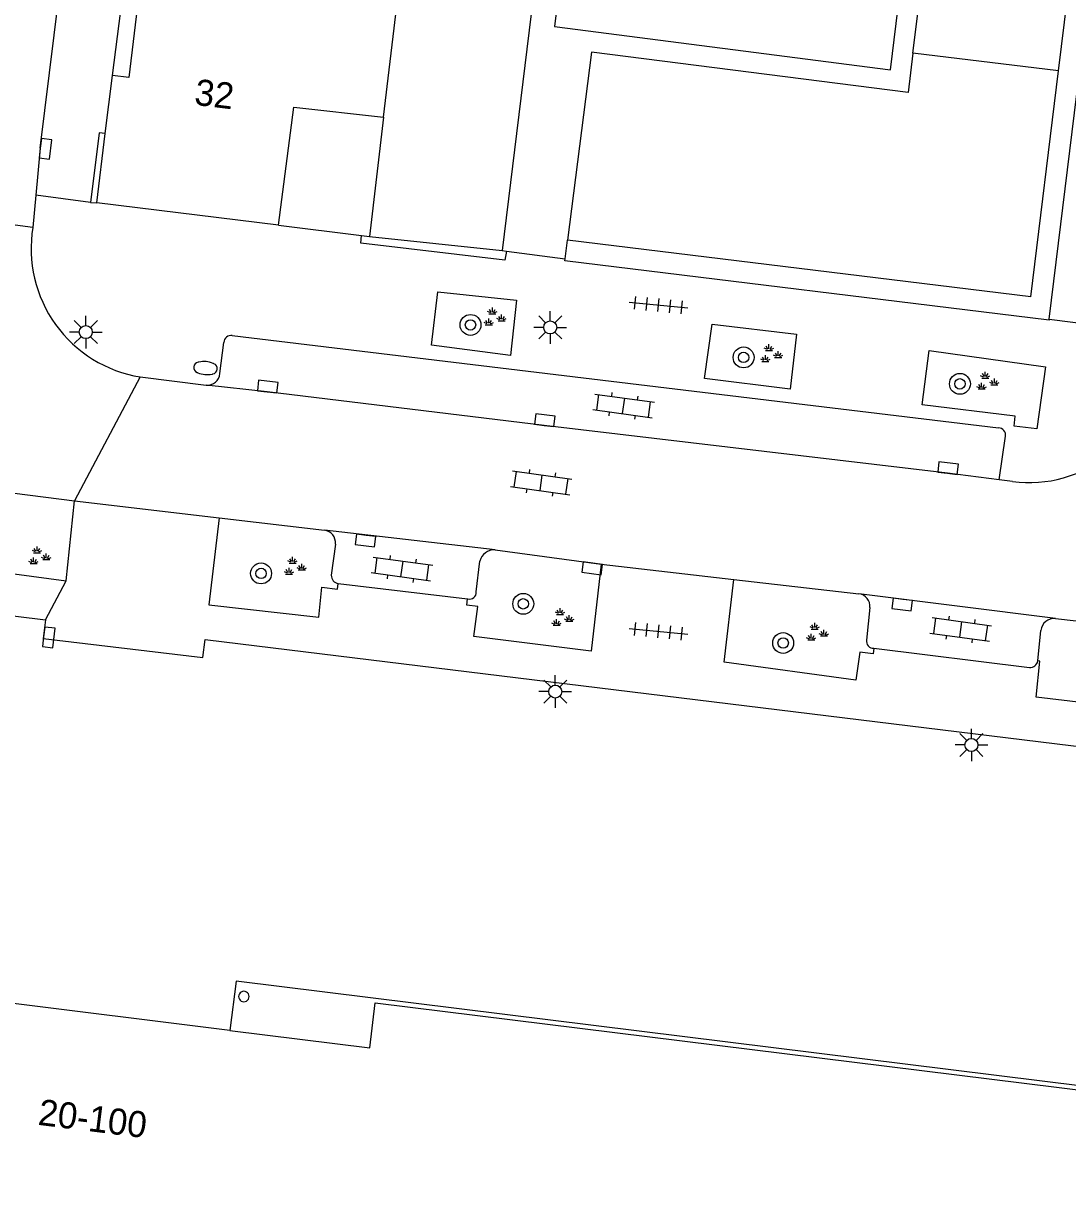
# Model space of a CAD drawing. Extents: x 131000 to 133014, y 396499 to 399001.
# Drawn here: x 132127.74 to 132167.75, y 396701.57 to 396746.51 of the extents above; entities that cross this region are included whole.
import ezdxf

# ---------------------------------------------------------------- set-up
doc = ezdxf.new("R2010")
doc.units = 0
for name, color, linetype in [('gg-afsc-erfafscheiding', 7, 'Continuous'), ('gg-anno-huisnummerreeks BGT', 7, 'Continuous'), ('gg-bbg-hoofdgebouw', 7, 'Continuous'), ('gg-bbg-luifel en loopbrug', 7, 'Continuous'), ('gg-bbg-onder overbouw', 7, 'Continuous'), ('gg-bbg-pand overbouw', 7, 'Continuous'), ('gg-bbg-pilaar onder overbouw', 7, 'Continuous'), ('gg-knt-verharding', 7, 'Continuous'), ('gg-knt-verharding nz', 7, 'Continuous'), ('gt-grn-groengrens', 7, 'Continuous'), ('gt-grn-weggrens', 7, 'Continuous'), ('gt-symb-boom', 7, 'Continuous'), ('gt-symb-brandkraan', 7, 'Continuous'), ('gt-symb-groenvak', 7, 'Continuous'), ('gt-symb-klinker verharding', 7, 'Continuous'), ('gt-symb-kolk', 7, 'Continuous'), ('gt-symb-lichtmast', 7, 'Continuous'), ('gt-symb-tegel verharding', 7, 'Continuous')]:
    doc.layers.add(name, color=color, linetype=linetype)

# ---------------------------------------------------------------- blocks, each defined once
blk = doc.blocks.new('gt0-KOLK')
at = {"layer": 'gt-symb-kolk'}
blk.add_lwpolyline([(0, 0), (0.375, 0), (0.375, 0.4), (-0.375, 0.4), (-0.375, 0), (0, 0)], dxfattribs=at)
blk = doc.blocks.new('gt0-TEG1')
at = {"layer": 'gt-symb-tegel verharding'}
for p, q in [((-1.125, 0), (1.125, 0)), ((-0.9, -0.25), (-0.9, 0.25)), ((-0.45, -0.25), (-0.45, 0.25)), ((0, -0.25), (0, 0.25)), ((0.45, -0.25), (0.45, 0.25)), ((0.9, -0.25), (0.9, 0.25))]:
    blk.add_line(p, q, dxfattribs=at)
blk = doc.blocks.new('gt0-KL1')
at = {"layer": 'gt-symb-klinker verharding'}
for p, q in [((-0.5, 0.3), (-0.5, 0.45)), ((0.5, 0.3), (0.5, 0.45)), ((-1.15, 0.3), (1.15, 0.3)), ((-1, -0.3), (-1, 0.3)), ((0, -0.3), (0, 0.3)), ((1, -0.3), (1, 0.3)), ((-1.15, -0.3), (1.15, -0.3)), ((-0.5, -0.45), (-0.5, -0.3)), ((0.5, -0.45), (0.5, -0.3))]:
    blk.add_line(p, q, dxfattribs=at)
blk = doc.blocks.new('gt0-BR')
at = {"layer": 'gt-symb-brandkraan'}
for centre, radius, start, end in [((-0.244, 0), 0.206, 107.5669, 252.4331), ((0.599, -2.664), 3, 106.892, 107.5669), ((0, -0.691), 0.938, 73.108, 106.892), ((-0.599, -2.664), 3, 72.4331, 73.108), ((0.244, 0), 0.206, 287.567, 72.4331), ((0.599, 2.664), 3, 252.4331, 253.108), ((0, 0.691), 0.938, 253.108, 286.8921), ((-0.599, 2.664), 3, 286.8921, 287.567)]:
    blk.add_arc(centre, radius, start, end, dxfattribs=at)
blk = doc.blocks.new('gt0-BOOM')
at = {"layer": 'gt-symb-boom'}
for radius in [0.4, 0.2]:
    blk.add_circle((0, 0), radius, dxfattribs=at)
blk = doc.blocks.new('gt0-GRVAK')
at = {"layer": 'gt-symb-groenvak'}
for p, q in [((-0.11, 0.189), (-0.228, 0.24)), ((-0.182, 0.153), (0.088, 0.153)), ((-0.091, 0.211), (-0.156, 0.322)), ((-0.047, 0.214), (-0.047, 0.393)), ((-0.004, 0.211), (0.061, 0.322)), ((0.015, 0.189), (0.133, 0.24)), ((0.262, -0.052), (0.197, 0.059)), ((0.305, -0.049), (0.305, 0.13)), ((0.349, -0.052), (0.414, 0.059)), ((-0.245, -0.228), (-0.363, -0.177)), ((-0.318, -0.264), (-0.047, -0.264)), ((-0.226, -0.206), (-0.291, -0.095)), ((-0.183, -0.203), (-0.183, -0.024)), ((-0.139, -0.206), (-0.074, -0.095)), ((-0.12, -0.228), (-0.002, -0.177)), ((0.243, -0.074), (0.125, -0.023)), ((0.17, -0.11), (0.441, -0.11)), ((0.368, -0.074), (0.486, -0.023))]:
    blk.add_line(p, q, dxfattribs=at)
blk = doc.blocks.new('gt0-LMAST')
at = {"layer": 'gt-symb-lichtmast'}
for p, q in [((-0.005, 0.246), (-0.005, 0.621)), ((-0.182, 0.173), (-0.447, 0.438)), ((0.172, 0.173), (0.437, 0.438)), ((-0.255, -0.004), (-0.63, -0.004)), ((-0.182, -0.181), (-0.447, -0.446)), ((-0.005, -0.254), (-0.005, -0.629)), ((0.437, -0.446), (0.172, -0.181)), ((0.245, -0.004), (0.62, -0.004))]:
    blk.add_line(p, q, dxfattribs=at)
blk.add_circle((-0.005, -0.004), 0.25, dxfattribs=at)

msp = doc.modelspace()

# ---------------------------------------------------------------- linework, layer by layer
at = {"layer": 'gg-afsc-erfafscheiding'}
msp.add_line((132140.997, 396738.349), (132146.08, 396737.81), dxfattribs=at)
at = {"layer": 'gg-bbg-hoofdgebouw'}
for p, q in [((132141.54, 396742.92), (132142.12, 396747.766)), ((132130.877, 396742.296), (132131.15, 396744.52)), ((132130.55, 396739.64), (132130.877, 396742.296)), ((132137.51, 396738.78), (132130.55, 396739.64)), ((132135.651, 396707.929), (132126.312, 396709.096))]:
    msp.add_line(p, q, dxfattribs=at)
for points in [[(132132.32, 396748.91), (132131.78, 396744.44), (132131.15, 396744.52)], [(132137.51, 396738.78), (132138.1, 396743.31), (132141.54, 396742.92)]]:
    msp.add_lwpolyline(points, dxfattribs=at)
at = {"layer": 'gg-bbg-luifel en loopbrug'}
for p, q in [((132141.54, 396742.92), (132140.997, 396738.349)), ((132137.51, 396738.78), (132140.699, 396738.386)), ((132140.699, 396738.386), (132140.997, 396738.349))]:
    msp.add_line(p, q, dxfattribs=at)
at = {"layer": 'gg-bbg-onder overbouw'}
msp.add_lwpolyline([(132135.651, 396707.929), (132141.008, 396707.259), (132141.222, 396708.986), (132183.114, 396703.797), (132182.918, 396702.064), (132187.037, 396701.565)], dxfattribs=at)
at = {"layer": 'gg-bbg-pand overbouw'}
msp.add_lwpolyline([(132187.037, 396701.565), (132187.261, 396703.438), (132135.886, 396709.821), (132135.651, 396707.929)], dxfattribs=at)
at = {"layer": 'gg-bbg-pilaar onder overbouw'}
for start, end in [(359.9993, 180.0007), (179.9993, 0.0007)]:
    msp.add_arc((132136.186, 396709.228), 0.2, start, end, dxfattribs=at)
at = {"layer": 'gg-knt-verharding'}
for p, q in [((132128.385, 396741.731), (132135.967, 396803.38)), ((132152.94, 396793.692), (132146.08, 396737.81)), ((132161.826, 396745.379), (132163.04, 396755.239)), ((132131.15, 396744.52), (132131.72, 396748.98)), ((132128.385, 396741.731), (132128.215, 396739.93)), ((132128.215, 396739.93), (132128.098, 396738.694)), ((132130.311, 396739.652), (132130.55, 396739.64)), ((132148.5, 396737.49), (132148.592, 396738.212)), ((132166.343, 396736.035), (132148.592, 396738.212)), ((132135.265, 396733.098), (132135.42, 396734.291)), ((132135.74, 396734.552), (132165.11, 396731.016)), ((132132.214, 396732.966), (132134.744, 396732.655)), ((132165.133, 396729.022), (132165.376, 396730.696)), ((132165.646, 396728.956), (132165.133, 396729.022)), ((132127.393, 396728.518), (132129.693, 396728.22)), ((132129.376, 396725.16), (132129.693, 396728.22)), ((132129.693, 396728.22), (132135.24, 396727.567)), ((132135.24, 396727.567), (132139.271, 396727.092)), ((132139.698, 396726.563), (132139.535, 396725.37)), ((132145.818, 396726.338), (132149.883, 396725.797)), ((132145.087, 396724.731), (132145.231, 396725.91)), ((132149.883, 396725.797), (132154.962, 396725.213)), ((132139.802, 396725.048), (132144.759, 396724.467)), ((132154.962, 396725.213), (132159.752, 396724.661)), ((132144.759, 396724.467), (132144.77, 396724.466)), ((132160.179, 396724.132), (132160.049, 396722.886)), ((132167.287, 396723.71), (132171.126, 396723.267)), ((132166.61, 396722.087), (132166.732, 396723.256)), ((132160.326, 396722.571), (132166.291, 396721.832))]:
    msp.add_line(p, q, dxfattribs=at)
for points in [[(132167.044, 396735.182), (132170.658, 396764.629), (132173.887, 396790.201)], [(132166.16, 396787.27), (132153.3, 396788.94), (132148.09, 396746.39), (132160.96, 396744.74), (132166.16, 396787.27)], [(132161.826, 396745.379), (132161.64, 396743.87), (132149.51, 396745.41), (132148.592, 396738.212)], [(132130.877, 396742.296), (132130.64, 396742.325), (132130.311, 396739.652)], [(132146.25, 396737.788), (132146.19, 396737.444), (132140.663, 396738.092), (132140.699, 396738.386)], [(132167.044, 396735.182), (132167.041, 396735.143), (132148.491, 396737.418), (132148.5, 396737.49)], [(132143.382, 396734.18), (132143.62, 396736.229), (132146.636, 396735.914), (132146.404, 396733.79), (132143.382, 396734.18)], [(132153.833, 396732.907), (132154.126, 396734.985), (132157.37, 396734.605), (132157.115, 396732.503), (132153.833, 396732.907)], [(132162.185, 396731.896), (132162.444, 396733.978), (132166.902, 396733.361), (132166.573, 396730.981), (132165.711, 396731.08), (132165.738, 396731.467), (132162.185, 396731.896)], [(132069.358, 396726.549), (132071.724, 396728.682), (132075.245, 396730.247), (132128.586, 396723.658)], [(132135.24, 396727.567), (132134.848, 396724.239), (132139.056, 396723.758), (132139.177, 396724.919), (132139.78, 396724.838), (132139.802, 396725.048)], [(132125.388, 396727.195), (132125.187, 396725.72), (132129.376, 396725.16)], [(132149.883, 396725.797), (132149.499, 396722.458), (132144.996, 396723.026), (132145.158, 396724.171), (132144.73, 396724.221), (132144.759, 396724.467)], [(132160.326, 396722.571), (132160.304, 396722.364), (132159.788, 396722.418), (132159.637, 396721.35), (132154.596, 396722.034), (132154.962, 396725.213)], [(132128.586, 396723.658), (132128.501, 396722.941), (132134.608, 396722.22), (132134.7, 396722.904), (132177.989, 396717.612)], [(132171.126, 396723.267), (132170.733, 396720.206), (132166.55, 396720.7), (132166.684, 396722.08), (132166.61, 396722.087)]]:
    msp.add_lwpolyline(points, dxfattribs=at)
for centre, radius, start, end in [((132133.018, 396737.886), 4.985, 170.6756, 260.7246), ((132135.688, 396734.289), 0.268, 78.9093, 179.4938), ((132166.257, 396733.904), 4.986, 262.9588, 353.4229), ((132134.779, 396733.142), 0.488, 265.9121, 354.8361), ((132165.101, 396730.738), 0.278, 351.2356, 88.2345), ((132139.207, 396726.603), 0.493, 355.3127, 82.5071), ((132145.769, 396725.788), 0.552, 84.9581, 167.2358), ((132139.857, 396725.366), 0.322, 179.2038, 260.1267), ((132144.841, 396724.704), 0.248, 253.4751, 6.3136), ((132159.688, 396724.172), 0.493, 355.3127, 82.5071), ((132167.234, 396723.208), 0.504, 83.9794, 174.5882), ((132160.31, 396722.836), 0.265, 169.116, 273.5385), ((132166.302, 396722.146), 0.314, 268.0495, 349.2263)]:
    msp.add_arc(centre, radius, start, end, dxfattribs=at)
at = {"layer": 'gg-knt-verharding nz'}
for p, q in [((132145.818, 396726.338), (132139.271, 396727.092)), ((132167.287, 396723.71), (132159.752, 396724.661))]:
    msp.add_line(p, q, dxfattribs=at)
msp.add_lwpolyline([(132165.133, 396729.022), (132163.148, 396729.279), (132147.694, 396731.11), (132137.082, 396732.4), (132134.744, 396732.655)], dxfattribs=at)
at = {"layer": 'gt-grn-groengrens'}
for p, q in [((132167.405, 396744.692), (132167.868, 396748.466)), ((132167.405, 396744.692), (132161.826, 396745.379)), ((132166.343, 396736.035), (132167.405, 396744.692))]:
    msp.add_line(p, q, dxfattribs=at)
at = {"layer": 'gt-grn-weggrens'}
for p, q in [((132130.311, 396739.652), (132128.215, 396739.93)), ((132128.098, 396738.694), (132121.927, 396739.496)), ((132146.08, 396737.81), (132146.25, 396737.788)), ((132146.25, 396737.788), (132148.5, 396737.49)), ((132167.044, 396735.182), (132171.379, 396734.643)), ((132132.214, 396732.966), (132129.693, 396728.22)), ((132128.586, 396723.658), (132129.376, 396725.16))]:
    msp.add_line(p, q, dxfattribs=at)

# ---------------------------------------------------------------- block references
at = {"layer": 'gt-symb-boom'}
for p in [(132144.872, 396734.961), (132155.337, 396733.716), (132163.627, 396732.702), (132136.845, 396725.44), (132146.892, 396724.274), (132156.852, 396722.774)]:
    msp.add_blockref('gt0-BOOM', p, dxfattribs=at)
at = {"layer": 'gt-symb-brandkraan', "rotation": 174.35845917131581}
msp.add_blockref('gt0-BR', (132134.715, 396733.308), dxfattribs=at)
at = {"layer": 'gt-symb-groenvak'}
for p in [(132145.755, 396735.23), (132156.357, 396733.825), (132164.642, 396732.772), (132128.31, 396726.079), (132138.102, 396725.681), (132148.353, 396723.715), (132158.112, 396723.153)]:
    msp.add_blockref('gt0-GRVAK', p, dxfattribs=at)
at = {"layer": 'gt-symb-klinker verharding'}
for p, rotation in [((132150.74, 396731.859), -7.87092049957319), ((132147.58, 396728.911), -7.870920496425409), ((132142.244, 396725.611), -7.870920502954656), ((132163.659, 396723.294), -7.870920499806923)]:
    msp.add_blockref('gt0-KL1', p, dxfattribs=dict(at, rotation=rotation))
at = {"layer": 'gt-symb-kolk'}
for p, rotation in [((132128.385, 396741.731), -96.94741065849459), ((132137.082, 396732.4), -6.226120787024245), ((132147.694, 396731.11), -6.932833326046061), ((132163.148, 396729.279), -6.761692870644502), ((132140.87, 396726.898), 173.54663023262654), ((132149.564, 396725.834), 172.32642806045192), ((132161.442, 396724.444), 172.84795923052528), ((132128.509, 396723.011), -96.79469842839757)]:
    msp.add_blockref('gt0-KOLK', p, dxfattribs=dict(at, rotation=rotation))
at = {"layer": 'gt-symb-lichtmast'}
for p in [(132130.134, 396734.69), (132147.931, 396734.869), (132148.126, 396720.915), (132164.073, 396718.87)]:
    msp.add_blockref('gt0-LMAST', p, dxfattribs=at)
at = {"layer": 'gt-symb-tegel verharding'}
for p, rotation in [((132152.074, 396735.721), -5.510976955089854), ((132152.074, 396723.223), -5.510976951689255)]:
    msp.add_blockref('gt0-TEG1', p, dxfattribs=dict(at, rotation=rotation))

# ---------------------------------------------------------------- texts
at = {"layer": 'gg-anno-huisnummerreeks BGT'}
for s, rotation, p in [('32', 353, (132134.26, 396743.401)), ('20-100', 352.9, (132128.268, 396704.316))]:
    msp.add_text(s, height=1, rotation=rotation, dxfattribs=at).set_placement(p)

doc.saveas('drawing.dxf')
